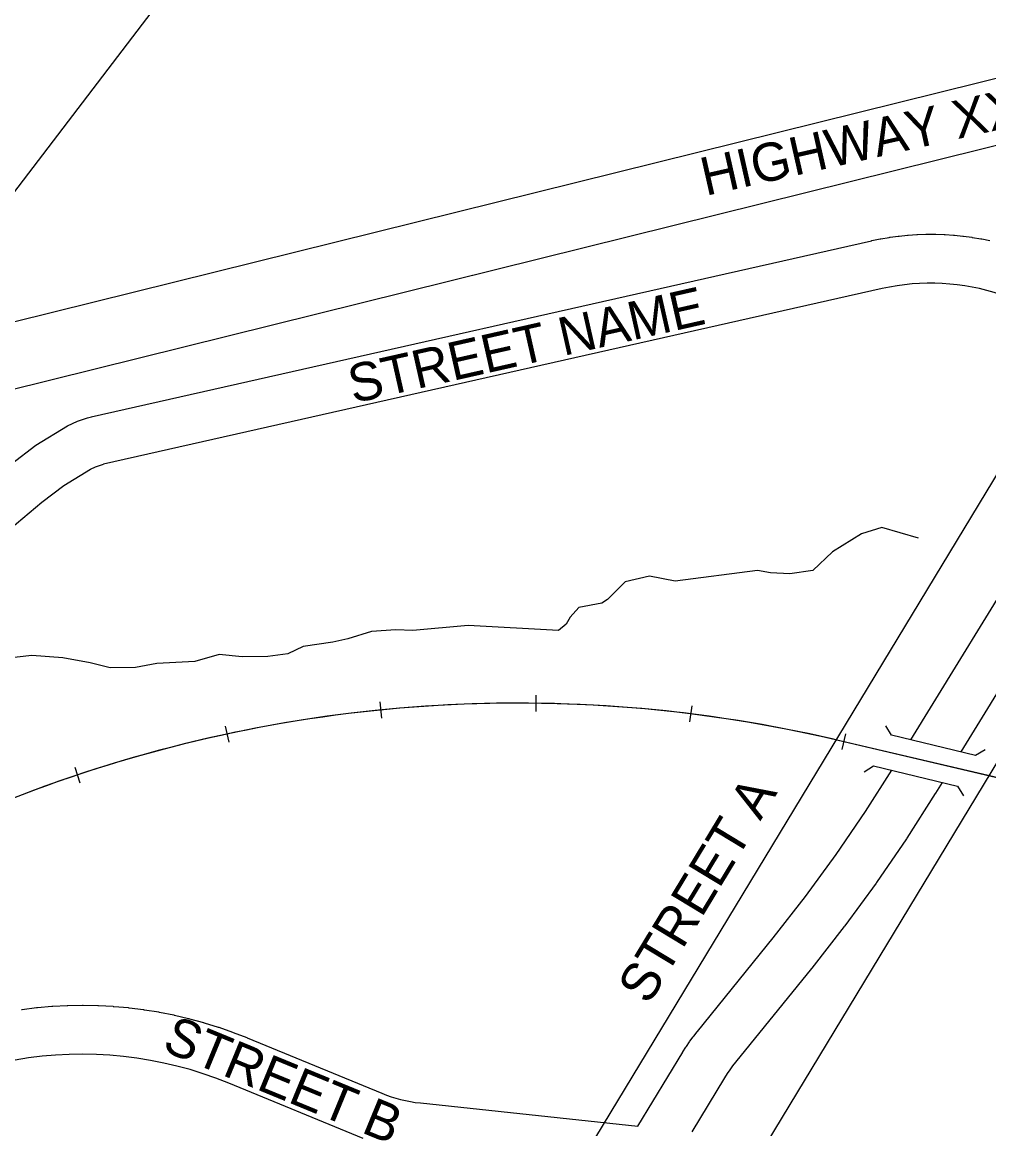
# Model space of a CAD drawing. Extents: x 599744 to 600217, y 4827560 to 4828065.
# Drawn here: x 600007.45 to 600025.18, y 4827998.23 to 4828018.52 of the extents above; entities that cross this region are included whole.
import ezdxf

# ---------------------------------------------------------------- set-up
doc = ezdxf.new("R2010")
doc.units = 0
doc.layers.add('G-ANNO-KEYP', color=7, linetype='Continuous')
doc.layers.add('G-TTLB-OTLN', color=7, linetype='Continuous')

msp = doc.modelspace()

# ---------------------------------------------------------------- linework, layer by layer
at = {"layer": 'G-ANNO-KEYP'}
for p, q in [((600002.376, 4828005.187), (600007.817, 4828009.72)), ((600016.874, 4828006.184), (600016.871, 4828005.884)), ((600014.012, 4828006.059), (600014.041, 4828005.76)), ((600019.735, 4828005.99), (600019.694, 4828005.693)), ((600011.18, 4828005.616), (600011.244, 4828005.323)), ((600023.395, 4828005.448), (600023.289, 4828005.622)), ((600051.095, 4827998.607), (600022.395, 4828005.359)), ((600022.552, 4828005.476), (600022.483, 4828005.184)), ((600024.936, 4828005.075), (600023.395, 4828005.448)), ((600025.11, 4828005.181), (600024.936, 4828005.075)), ((600008.418, 4828004.86), (600008.512, 4828004.575)), ((600022.892, 4828004.779), (600023.066, 4828004.885)), ((600023.066, 4828004.885), (600024.607, 4828004.512)), ((600024.607, 4828004.512), (600024.713, 4828004.338))]:
    msp.add_line(p, q, dxfattribs=at)
for points in [[(600005.072, 4828012.476), (600027.218, 4828017.966), (600028.959, 4828018.431), (600030.677, 4828018.956), (600032.375, 4828019.541), (600034.051, 4828020.187), (600035.703, 4828020.892), (600037.329, 4828021.656), (600038.687, 4828022.354)], [(600027.512, 4828016.804), (600003.91, 4828010.952)], [(600008.72, 4828011.286), (600023.028, 4828014.514), (600023.035, 4828014.516), (600023.035, 4828014.516), (600023.186, 4828014.547), (600023.2, 4828014.55), (600023.201, 4828014.55), (600023.352, 4828014.576), (600023.367, 4828014.578), (600023.368, 4828014.579), (600023.52, 4828014.599), (600023.525, 4828014.6), (600023.535, 4828014.601), (600023.688, 4828014.617), (600023.688, 4828014.617), (600023.703, 4828014.618), (600023.857, 4828014.629), (600023.858, 4828014.628), (600023.872, 4828014.63), (600024.026, 4828014.635), (600024.027, 4828014.634), (600024.041, 4828014.635), (600024.195, 4828014.635), (600024.197, 4828014.634), (600024.21, 4828014.635), (600024.364, 4828014.63), (600024.367, 4828014.628), (600024.379, 4828014.629), (600024.532, 4828014.618), (600024.536, 4828014.617), (600024.548, 4828014.617), (600024.701, 4828014.601), (600024.705, 4828014.599), (600024.716, 4828014.599), (600024.868, 4828014.578), (600024.873, 4828014.576), (600024.883, 4828014.576), (600025.035, 4828014.55), (600025.041, 4828014.547), (600025.05, 4828014.547), (600025.2, 4828014.516)], [(600023.361, 4828013.665), (600023.222, 4828013.636), (600008.949, 4828010.415)], [(600028.141, 4828012.503), (600025.543, 4828013.477), (600025.409, 4828013.525), (600025.278, 4828013.567), (600025.144, 4828013.604), (600025.009, 4828013.637), (600024.875, 4828013.665), (600024.738, 4828013.688), (600024.601, 4828013.707), (600024.463, 4828013.721), (600024.325, 4828013.731), (600024.187, 4828013.736), (600024.048, 4828013.736), (600023.91, 4828013.731), (600023.773, 4828013.722), (600023.635, 4828013.707), (600023.498, 4828013.689), (600023.361, 4828013.665)], [(600023.749, 4828005.364), (600028.14, 4828012.504)], [(600028.997, 4828012.181), (600024.667, 4828005.141)], [(600007.257, 4828010.424), (600007.707, 4828010.767), (600008.284, 4828011.123), (600008.472, 4828011.208), (600008.656, 4828011.269), (600008.728, 4828011.287)], [(600007.817, 4828009.72), (600008.217, 4828010.024), (600008.708, 4828010.327), (600008.8, 4828010.369), (600008.908, 4828010.405), (600008.949, 4828010.415)], [(600023.89, 4828009.062), (600023.22, 4828009.259), (600022.844, 4828009.142), (600022.312, 4828008.81), (600021.954, 4828008.467), (600021.531, 4828008.405), (600021.177, 4828008.427), (600020.939, 4828008.467), (600019.427, 4828008.27), (600018.959, 4828008.362), (600018.511, 4828008.26), (600018.187, 4828007.938), (600018.083, 4828007.868), (600017.664, 4828007.79), (600017.504, 4828007.614), (600017.433, 4828007.483), (600017.289, 4828007.366), (600015.631, 4828007.462), (600014.619, 4828007.371), (600014.306, 4828007.379), (600013.863, 4828007.348), (600013.426, 4828007.215)], [(600013.426, 4828007.215), (600013.152, 4828007.153), (600012.61, 4828007.077), (600012.325, 4828006.943), (600011.962, 4828006.889), (600011.49, 4828006.884), (600011.067, 4828006.93), (600010.62, 4828006.798), (600009.927, 4828006.766), (600009.535, 4828006.689), (600009.066, 4828006.681), (600008.701, 4828006.773), (600008.202, 4828006.864), (600007.632, 4828006.912), (600006.873, 4828006.824), (600006.168, 4828006.464), (600005.605, 4828006.366), (600004.645, 4828006.636), (600004.449, 4828006.734)], [(600051.095, 4827998.607), (600022.395, 4828005.359), (600022.332, 4828005.373), (600021.896, 4828005.471), (600021.46, 4828005.561), (600021.022, 4828005.643), (600020.585, 4828005.716), (600020.145, 4828005.782), (600019.704, 4828005.843), (600019.262, 4828005.893), (600018.819, 4828005.936), (600018.374, 4828005.971), (600017.929, 4828006), (600017.485, 4828006.019), (600017.041, 4828006.032), (600016.596, 4828006.037), (600016.15, 4828006.033), (600015.707, 4828006.022), (600015.26, 4828006.004), (600014.818, 4828005.977), (600014.372, 4828005.943), (600013.93, 4828005.9), (600013.487, 4828005.851)], [(600013.487, 4828005.851), (600013.047, 4828005.795), (600012.605, 4828005.73), (600012.167, 4828005.655), (600011.731, 4828005.576), (600011.292, 4828005.487), (600010.859, 4828005.393), (600010.426, 4828005.29), (600009.994, 4828005.177), (600009.566, 4828005.06), (600009.139, 4828004.935), (600008.713, 4828004.799), (600008.291, 4828004.66), (600007.872, 4828004.514), (600007.454, 4828004.357), (599995.35, 4827999.732)], [(600019.76, 4827999.92), (600019.768, 4827999.932), (600019.769, 4827999.932), (600019.832, 4828000.012), (600019.832, 4828000.012), (600019.836, 4828000.018), (600021.225, 4828001.733), (600021.817, 4828002.489), (600022.382, 4828003.26), (600022.921, 4828004.048), (600023.403, 4828004.805)], [(600024.324, 4828004.582), (600024.201, 4828004.383), (600024.197, 4828004.378), (600024.197, 4828004.377), (600023.676, 4828003.559), (600023.668, 4828003.548), (600023.668, 4828003.547), (600023.12, 4828002.746), (600023.112, 4828002.735), (600023.112, 4828002.734), (600022.539, 4828001.952), (600022.531, 4828001.941), (600022.53, 4828001.94), (600021.933, 4828001.178), (600021.933, 4828001.178), (600021.932, 4828001.177), (600021.932, 4828001.177), (600021.932, 4828001.177), (600021.927, 4828001.171), (600020.538, 4827999.455), (600020.482, 4827999.384), (600020.431, 4827999.314), (600020.383, 4827999.243), (600020.335, 4827999.167), (600019.734, 4827998.176)], [(600007.44, 4828000.42), (600007.455, 4828000.422), (600007.456, 4828000.422), (600007.718, 4828000.454), (600007.718, 4828000.454), (600007.719, 4828000.454), (600007.719, 4828000.454), (600007.719, 4828000.454), (600007.735, 4828000.456), (600007.999, 4828000.479), (600008, 4828000.479), (600008.015, 4828000.48), (600008.28, 4828000.494), (600008.281, 4828000.493), (600008.295, 4828000.494), (600008.561, 4828000.498), (600008.563, 4828000.498), (600008.576, 4828000.498), (600008.841, 4828000.493), (600008.844, 4828000.492), (600008.857, 4828000.493), (600009.122, 4828000.478), (600009.126, 4828000.477), (600009.138, 4828000.477), (600009.402, 4828000.453), (600009.406, 4828000.451), (600009.418, 4828000.451), (600009.681, 4828000.418), (600009.686, 4828000.416), (600009.696, 4828000.416), (600009.958, 4828000.374), (600009.964, 4828000.371)], [(600009.964, 4828000.371), (600009.974, 4828000.371), (600010.234, 4828000.319), (600010.24, 4828000.316), (600010.249, 4828000.316), (600010.507, 4828000.255), (600010.514, 4828000.252), (600010.523, 4828000.251), (600010.778, 4828000.181), (600010.786, 4828000.177), (600010.794, 4828000.177), (600011.047, 4828000.098), (600011.055, 4828000.093), (600011.062, 4828000.093), (600011.312, 4828000.005), (600011.321, 4828000), (600011.327, 4827999.999), (600011.574, 4827999.903), (600011.578, 4827999.9), (600011.581, 4827999.9), (600014.047, 4827998.885), (600014.135, 4827998.85), (600014.221, 4827998.82), (600014.308, 4827998.793), (600014.395, 4827998.769), (600014.483, 4827998.749), (600014.573, 4827998.731), (600014.662, 4827998.717), (600014.756, 4827998.705), (600018.743, 4827998.281)], [(600018.745, 4827998.28), (600019.568, 4827999.636), (600019.571, 4827999.641), (600019.572, 4827999.642), (600019.626, 4827999.728), (600019.634, 4827999.74), (600019.634, 4827999.741), (600019.691, 4827999.825), (600019.7, 4827999.837), (600019.7, 4827999.838), (600019.76, 4827999.92)], [(600013.709, 4827998.052), (600011.242, 4827999.067), (600011.007, 4827999.159), (600010.771, 4827999.242), (600010.534, 4827999.316), (600010.293, 4827999.381), (600010.051, 4827999.438), (600009.806, 4827999.487), (600009.56, 4827999.527), (600009.313, 4827999.558), (600009.065, 4827999.58), (600008.816, 4827999.594), (600008.567, 4827999.599), (600008.318, 4827999.595), (600008.069, 4827999.582), (600007.821, 4827999.561), (600007.574, 4827999.53), (600007.327, 4827999.491)]]:
    msp.add_lwpolyline(points, dxfattribs=at)
msp.add_lwpolyline([(600010.535, 4827985.796), (600028.374, 4828015.258), (600030.714, 4828013.841), (600012.874, 4827984.379)], close=True, dxfattribs=at)
msp.add_lwpolyline([(600010.535, 4827985.796), (600028.374, 4828015.258), (600030.714, 4828013.841), (600012.874, 4827984.379)], close=True, dxfattribs=at)
msp.add_arc((600016.556, 4827980.534), 25.502, 76.7641, 110.9105, dxfattribs=at)
at = {"layer": 'G-TTLB-OTLN'}
msp.add_lwpolyline([(599983.747, 4827984.522), (600022.202, 4828034.93), (600058.02, 4828007.605), (600019.565, 4827957.197)], close=True, dxfattribs=at)

# ---------------------------------------------------------------- texts
at = {"layer": 'G-ANNO-KEYP'}
for s, rotation, p in [('HIGHWAY XXX', 12.7169, (600019.987, 4828015.335)), ('STREET NAME', 12.7173, (600013.524, 4828011.531)), ('STREET A', 58.8043, (600018.942, 4828000.485)), ('STREET B', 337.627, (600009.997, 4827999.678))]:
    msp.add_text(s, height=0.7, rotation=rotation, dxfattribs=at).set_placement(p)

doc.saveas('drawing.dxf')
